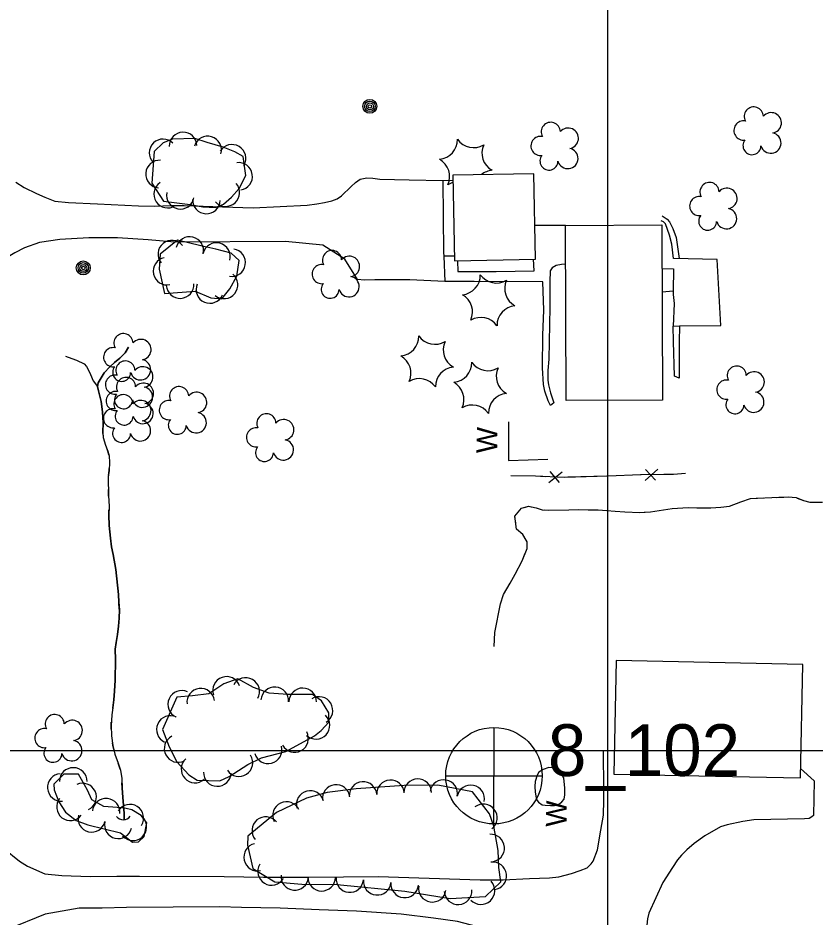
# Model space of a CAD drawing. Extents: x 591954 to 597000, y 198576 to 213500.
# Drawn here: x 594328.8 to 594560.2, y 210451.7 to 210712.6 of the extents above; entities that cross this region are included whole.
import ezdxf

# ---------------------------------------------------------------- set-up
doc = ezdxf.new("R2010")
doc.units = 0
for name, color, linetype in [('Level 10', 7, 'Continuous'), ('Level 12', 7, 'Continuous'), ('Level 14', 7, 'Continuous'), ('Level 15', 7, 'Continuous'), ('Level 17', 7, 'Continuous'), ('Level 18', 7, 'Continuous'), ('Level 19', 7, 'Continuous'), ('Level 4', 7, 'Continuous')]:
    doc.layers.add(name, color=color, linetype=linetype)

msp = doc.modelspace()

# ---------------------------------------------------------------- linework, layer by layer
at = {"layer": 'Level 10'}
for p, q in [((594500, 210000), (594500, 211500)), ((593000, 210500), (595000, 210500)), ((593000, 210500), (595000, 210500)), ((594500, 209500), (594500, 210500))]:
    msp.add_line(p, q, dxfattribs=at)
at = {"layer": 'Level 12'}
for points in [[(594478.54, 210667.39), (594455.06, 210666.95), (594455.53, 210642.11), (594479.01, 210642.55), (594478.54, 210667.39)], [(594487.7, 210652.35), (594515.66, 210652.5), (594515.94, 210601.7), (594487.97, 210601.55), (594487.7, 210652.35)], [(594515.73, 210639.84), (594519.11, 210639.82), (594518.98, 210633.26), (594515.77, 210633.05)], [(594556.61, 210524.94), (594502.48, 210526.08), (594501.79, 210493.18), (594555.92, 210492.04), (594556.61, 210524.94)]]:
    msp.add_lwpolyline(points, dxfattribs=at)
at = {"layer": 'Level 14'}
for centre, radius in [((594430.96, 210686.93), 2.02), ((594430.96, 210686.94), 1.52), ((594430.97, 210686.9), 1.01), ((594430.97, 210686.91), 0.502), ((594347.79, 210640.04), 2.02), ((594347.79, 210640.05), 1.52), ((594347.8, 210640.01), 1.01), ((594347.8, 210640.02), 0.502)]:
    msp.add_circle(centre, radius, dxfattribs=at)
at = {"layer": 'Level 15'}
for p, q in [((594482.94, 210577.78), (594486.78, 210580.88)), ((594483.23, 210581.01), (594485.91, 210577.74)), ((594510.88, 210578.33), (594514.55, 210581.63)), ((594511, 210581.58), (594513.84, 210578.45))]:
    msp.add_line(p, q, dxfattribs=at)
for points in [[(594471.18, 210595.36), (594471.18, 210584.16), (594482.63, 210584.55)], [(594471.9, 210579.82), (594479.01, 210579.67), (594487.43, 210579.36), (594500.13, 210579.72), (594509.47, 210580.05), (594519.1, 210580.2), (594522.54, 210580.52)], [(594471.9, 210579.82), (594479.01, 210579.67), (594481.85, 210579.56)], [(594488.43, 210579.39), (594499.74, 210579.71)], [(594499.74, 210579.71), (594500.13, 210579.72), (594509.47, 210580.05), (594509.69, 210580.05)], [(594516.28, 210580.16), (594519.1, 210580.2), (594522.54, 210580.52)], [(594487.26, 210492.09), (594485.82, 210494.45), (594484.38, 210494.99), (594482.88, 210495.1), (594481.22, 210494.53), (594479.99, 210493.7), (594479.53, 210492.85), (594478.93, 210490.99), (594478.86, 210489.54), (594478.96, 210487.93), (594479.24, 210486.31), (594479.57, 210485.52), (594479.94, 210484.99), (594480.93, 210484.26), (594481.86, 210484.1), (594483.4, 210484.06), (594484.53, 210484.08), (594485.43, 210484.23), (594486.15, 210484.61), (594486.72, 210485.12), (594487.36, 210485.9), (594487.55, 210487.14), (594487.55, 210487.97), (594487.54, 210489.05)], [(594487.54, 210489.05), (594487.26, 210492.09)]]:
    msp.add_lwpolyline(points, dxfattribs=at)
msp.add_arc((594359.4, 210482.39), 2.5, 217.7649, 324.0045, dxfattribs=at)
at = {"layer": 'Level 17'}
for points in [[(594328.2, 210664.89), (594330.67, 210663.33), (594334.18, 210661.64), (594336.66, 210660.6), (594339.55, 210659.41), (594343.47, 210659.02), (594351.91, 210658.59), (594363.84, 210658.05), (594368.42, 210657.99), (594373.17, 210658.11), (594377.07, 210658.12), (594388.15, 210657.73), (594397.09, 210657.47), (594412.81, 210658.27), (594415.61, 210658.63), (594417.84, 210659.07), (594419.91, 210659.54), (594421.5, 210660.13), (594422.7, 210660.92), (594425.54, 210663.71), (594426.75, 210664.82), (594428.19, 210665.78), (594430.05, 210666.17), (594431.79, 210666.04), (594433.86, 210665.78), (594442.37, 210665.64), (594452.13, 210665.44)], [(594452.13, 210665.44), (594455.09, 210665.48)], [(594452.13, 210665.44), (594452.32, 210644.51), (594452.43, 210643.41)], [(594519.14, 210642.78), (594518.64, 210646.92), (594517.93, 210649.56), (594516.75, 210652.82), (594516.18, 210653.43), (594515.53, 210653.75)], [(594515.77, 210655.2), (594517.23, 210654.23), (594517.92, 210653.42), (594518.89, 210651.49), (594519.86, 210648.86), (594520.71, 210642.75)], [(594487.7, 210652.33), (594478.83, 210652.32)], [(594357.68, 210648.76), (594349.37, 210648.82), (594341.03, 210648.32), (594335.11, 210647.41), (594330.77, 210645.84), (594327.89, 210644.39), (594326.51, 210643.53), (594325.33, 210642.65), (594323.31, 210640.75)], [(594452.68, 210636.09), (594442.55, 210636.61), (594432.41, 210636.63), (594429.39, 210636.44), (594427.35, 210636.71), (594423.69, 210642.56), (594417.28, 210646.62), (594406.44, 210647.68), (594374.3, 210647.55), (594366.58, 210648.17), (594357.68, 210648.76)], [(594455.51, 210643.45), (594452.43, 210643.41)], [(594452.43, 210643.41), (594452.68, 210636.09)], [(594456.43, 210642.13), (594456.45, 210639.01), (594467.58, 210639.02), (594478.67, 210639.2), (594478.47, 210642.55)], [(594518.98, 210633.26), (594518.98, 210632.31), (594519.29, 210629.71), (594518.98, 210623.15), (594520.82, 210623.23), (594532.86, 210623.29), (594531.76, 210642.53), (594519.14, 210642.78)], [(594487.76, 210641.12), (594486.57, 210641.08), (594485.04, 210640.76), (594483.84, 210640.08), (594483.25, 210639.15), (594483.21, 210635.99), (594483.21, 210628.67), (594482.95, 210613.58), (594482.6, 210610.3), (594482.61, 210607.49), (594482.81, 210606.11), (594483.37, 210603.8), (594484.06, 210601.72), (594484.35, 210600.92), (594483.41, 210600.14), (594482.71, 210601.46), (594481.77, 210604.25), (594481.38, 210606.24), (594481.04, 210611.03), (594481.15, 210620.51), (594481.49, 210627.75), (594481.2, 210636.02), (594461.25, 210636.12), (594452.68, 210636.09)], [(594519.39, 210608.59), (594519.13, 210618.7), (594518.98, 210623.16)], [(594520.82, 210623.23), (594520.78, 210618.64), (594520.71, 210608.06), (594519.39, 210608.59)], [(594498.92, 210488.71), (594498.73, 210499.93), (594501.94, 210500.08)], [(594559.93, 210491.23), (594555.97, 210494.83)], [(594559.93, 210491.23), (594559.72, 210481.18), (594559.28, 210480.74), (594558.48, 210480.31), (594557.1, 210480.19), (594542.37, 210479.92), (594539.17, 210479.39), (594534.67, 210478.48), (594532.74, 210477.81), (594528.2, 210475.21), (594525.07, 210473.01), (594522.99, 210471.2), (594521.4, 210469.61), (594520.25, 210468.28), (594518.79, 210466.08), (594516.03, 210461.73), (594511.96, 210452.83), (594511.57, 210451.2), (594510.21, 210438.17), (594509.28, 210424.01), (594508.43, 210412.49), (594500.24, 210412.55)], [(594324.69, 210471.61), (594329.24, 210467.93), (594331.56, 210466.43), (594336.62, 210464.23), (594341.54, 210463.71), (594349.83, 210463.48), (594357.51, 210463.56), (594364.07, 210463.52), (594388.67, 210463.4), (594400.13, 210463.27), (594413.27, 210463.26), (594433.36, 210463.43), (594463.02, 210462.51), (594469.69, 210462.45), (594477.3, 210462.88), (594483.06, 210463.09), (594485.84, 210463.33), (594489.49, 210464.3), (594492.03, 210465.15), (594493.99, 210465.99), (594495.17, 210467.1), (594495.78, 210467.9), (594496.99, 210471.16), (594497.98, 210476.92), (594498.76, 210481.22), (594498.92, 210485.56), (594498.92, 210488.71)], [(594478.3, 210413.08), (594478.16, 210414.7), (594477.11, 210432.33), (594475.7, 210440.7), (594474.65, 210442.4), (594473.14, 210444.01), (594471.33, 210445.28), (594464.1, 210448.4), (594456.4, 210450.38), (594449.44, 210451.4), (594440.02, 210452.52), (594427.11, 210453.36), (594416.29, 210453.79), (594404.9, 210454.25), (594393.69, 210454.49), (594387.41, 210454.61), (594360.3, 210454.44), (594353.28, 210454.29), (594346.56, 210454.21), (594336.68, 210452.55), (594325.77, 210448.11)]]:
    msp.add_lwpolyline(points, dxfattribs=at)
at = {"layer": 'Level 18'}
for points in [[(594371.11, 210659.38), (594378.85, 210658.43), (594382.47, 210657.72), (594386.19, 210657.57), (594388.52, 210658.51), (594390.8, 210660.56), (594393, 210663.1), (594394.97, 210666.9), (594394.15, 210672.39), (594391.82, 210673.77), (594388.38, 210675.1), (594383.78, 210676.48), (594380.18, 210677.63), (594373.72, 210677.43), (594370.96, 210676.35), (594368.32, 210673.79), (594367.65, 210664.64), (594371.11, 210659.38)], [(594371.34, 210632.64), (594380.27, 210633.34), (594384.84, 210631.35), (594388.01, 210631.07), (594390.36, 210633.94), (594392.34, 210637.63), (594393.06, 210642.15), (594390.69, 210644.36), (594386.26, 210645.52), (594381.9, 210646.47), (594375.13, 210648.08), (594370.13, 210644.02), (594369.84, 210639.64), (594371.34, 210632.64)], [(594406.61, 210499.74), (594414.85, 210504.23), (594416.82, 210505.82), (594419.03, 210508.2), (594419.06, 210510.96), (594416.96, 210514.4), (594414.27, 210516.21), (594407.19, 210516.25), (594401.7, 210516.65), (594397.19, 210518.25), (594392.65, 210520.8), (594388.57, 210519.39), (594384.23, 210516.41), (594379.5, 210515.85), (594374.99, 210515.46), (594370.74, 210506.08), (594372.7, 210501.03), (594374.96, 210496.72), (594378.4, 210492.9), (594380.8, 210491.41), (594387.45, 210491.18), (594390.15, 210492.48), (594395.51, 210495.94), (594399.56, 210497.85), (594406.61, 210499.74)], [(594362.07, 210473.42), (594363.78, 210473.5), (594365.43, 210475.02), (594366.23, 210478.99), (594364.6, 210481.12), (594361.9, 210482.81), (594360.25, 210483.2), (594357.61, 210483.44), (594353.72, 210483.8), (594350.28, 210485.74), (594348.98, 210488.49), (594346.44, 210493.1), (594342.15, 210493.14), (594339.22, 210490.26), (594339.36, 210488.55), (594340.74, 210485.11), (594342.6, 210482.16), (594345.76, 210479.71), (594349.11, 210478.43), (594358.6, 210476.1), (594362.07, 210473.42)], [(594466.97, 210478.02), (594465.69, 210481.6), (594460.74, 210488), (594450.69, 210489.95), (594440.96, 210489.81), (594426.96, 210488.91), (594418.61, 210487.84), (594412.6, 210486.22), (594403.85, 210482.04), (594395.51, 210475.15)], [(594395.51, 210475.15), (594395.47, 210472.49), (594397, 210465.75), (594403.4, 210461.88), (594411.2, 210461.19), (594421.47, 210461.09), (594441.16, 210459.18), (594454.28, 210457.08), (594464.53, 210457.69), (594468.98, 210461.85), (594468.42, 210466.01), (594468.18, 210471.01), (594466.97, 210478.02)]]:
    msp.add_lwpolyline(points, dxfattribs=at)
for centre, radius, start, end in [((594542.4, 210683.99), 2.78, 1.3946, 209.1675), ((594547.45, 210682.13), 2.97, 278.4237, 139.6575), ((594483.48, 210679.52), 2.78, 1.3946, 209.1675), ((594539.4, 210679.91), 2.78, 78.0716, 279.0826), ((594488.53, 210677.66), 2.97, 278.4237, 139.6575), ((594547.33, 210676.28), 2.97, 196.0745, 79.0477), ((594450.66, 210677.29), 5.72, 275.2113, 0.9762), ((594461.06, 210680.68), 5.72, 215.2113, 300.9762), ((594480.48, 210675.44), 2.78, 78.0716, 279.0826), ((594541.87, 210675.51), 2.61, 140.7797, 358.7123), ((594390.96, 210671.84), 4, 329.4135, 149.3982), ((594469.21, 210673.37), 5.72, 155.2113, 240.9762), ((594488.42, 210671.81), 2.97, 196.0745, 79.0477), ((594448.41, 210666.58), 5.72, 335.2113, 60.9762), ((594482.95, 210671.04), 2.61, 140.7797, 358.7123), ((594466.95, 210662.67), 5.72, 95.2113, 129.2172), ((594456.55, 210659.27), 5.72, 104.6616, 120.9762), ((594529.55, 210662.07), 2.78, 1.3946, 209.1675), ((594534.59, 210660.21), 2.97, 278.4237, 139.6575), ((594526.55, 210658), 2.78, 78.0716, 279.0826), ((594529.01, 210653.6), 2.61, 140.7797, 358.7123), ((594534.48, 210654.36), 2.97, 196.0745, 79.0477), ((594419.98, 210642.32), 2.78, 1.3946, 209.1675), ((594425.02, 210640.46), 2.97, 278.4237, 139.6575), ((594416.98, 210638.24), 2.78, 78.0716, 279.0826), ((594424.91, 210634.61), 2.97, 196.0745, 79.0477), ((594457.3, 210637.96), 5.72, 275.2113, 0.9762), ((594467.7, 210641.36), 5.72, 215.2113, 300.9762), ((594384.52, 210633.78), 4, 156.5045, 336.4892), ((594419.44, 210633.84), 2.61, 140.7797, 358.7123), ((594475.84, 210634.05), 5.72, 155.2113, 240.9762), ((594455.04, 210627.26), 5.72, 335.2113, 60.9762), ((594473.59, 210623.35), 5.72, 95.2113, 180.9762), ((594463.18, 210619.95), 5.72, 35.2113, 120.9762), ((594359.46, 210618.21), 2.78, 1.3946, 209.1675), ((594364.51, 210616.35), 2.97, 278.4237, 139.6575), ((594439.44, 210620.21), 5.72, 275.2113, 0.9762), ((594449.84, 210623.6), 5.72, 215.2113, 300.9762), ((594457.98, 210616.29), 5.72, 155.2113, 240.9762), ((594356.46, 210614.13), 2.78, 78.0716, 279.0826), ((594437.18, 210609.5), 5.72, 335.2113, 60.9762), ((594358.93, 210609.73), 2.61, 140.7797, 358.7123), ((594360.01, 210610.26), 2.78, 1.3946, 209.1675), ((594364.4, 210610.5), 2.97, 196.0745, 79.0477), ((594365.05, 210608.4), 2.97, 278.4237, 139.6575), ((594455.72, 210605.59), 5.72, 95.2113, 180.9762), ((594454.82, 210612.55), 5.72, 275.2113, 0.9762), ((594465.22, 210615.94), 5.72, 215.2113, 300.9762), ((594473.36, 210608.64), 5.72, 155.2113, 240.9762), ((594537.45, 210608.8), 2.78, 1.3946, 209.1675), ((594357.01, 210606.18), 2.78, 78.0716, 279.0826), ((594360.19, 210605.51), 2.78, 1.3946, 209.1675), ((594542.49, 210606.94), 2.97, 278.4237, 139.6575), ((594365.23, 210603.65), 2.97, 278.4237, 139.6575), ((594445.32, 210602.19), 5.72, 35.2113, 120.9762), ((594452.56, 210601.84), 5.72, 335.2113, 60.9762), ((594534.45, 210604.72), 2.78, 78.0716, 279.0826), ((594357.19, 210601.43), 2.78, 78.0716, 279.0826), ((594359.43, 210600.5), 2.78, 1.3946, 209.1675), ((594359.47, 210601.79), 2.61, 140.7797, 358.7123), ((594364.94, 210602.55), 2.97, 196.0745, 79.0477), ((594375.61, 210602.84), 2.78, 1.3946, 209.1675), ((594380.66, 210600.99), 2.97, 278.4237, 139.6575), ((594471.1, 210597.93), 5.72, 95.2113, 180.9762), ((594542.38, 210601.09), 2.97, 196.0745, 79.0477), ((594364.48, 210598.64), 2.97, 278.4237, 139.6575), ((594365.12, 210597.8), 2.97, 196.0745, 79.0477), ((594372.61, 210598.77), 2.78, 78.0716, 279.0826), ((594536.91, 210600.32), 2.61, 140.7797, 358.7123), ((594356.43, 210596.42), 2.78, 78.0716, 279.0826), ((594359.65, 210597.03), 2.61, 140.7797, 358.7123), ((594380.54, 210595.13), 2.97, 196.0745, 79.0477), ((594460.7, 210594.53), 5.72, 35.2113, 120.9762), ((594364.37, 210592.78), 2.97, 196.0745, 79.0477), ((594375.08, 210594.37), 2.61, 140.7797, 358.7123), ((594400.92, 210594.95), 2.78, 1.3946, 209.1675), ((594405.96, 210593.09), 2.97, 278.4237, 139.6575), ((594358.9, 210592.02), 2.61, 140.7797, 358.7123), ((594397.92, 210590.87), 2.78, 78.0716, 279.0826), ((594405.85, 210587.24), 2.97, 196.0745, 79.0477), ((594400.38, 210586.47), 2.61, 140.7797, 358.7123), ((594339.51, 210507.67), 2.78, 1.3946, 209.1675), ((594344.56, 210505.81), 2.97, 278.4237, 139.6575), ((594336.51, 210503.59), 2.78, 78.0716, 279.0826), ((594344.44, 210499.96), 2.97, 196.0745, 79.0477), ((594338.98, 210499.19), 2.61, 140.7797, 358.7123), ((594428.99, 210486.94), 4, 3.6813, 183.666), ((594436.97, 210487.45), 4, 3.6813, 183.666), ((594444.86, 210487.77), 4, 0.8265, 180.8111), ((594452.39, 210487.49), 4, 349.0424, 169.0271), ((594413.67, 210484.34), 4, 15.0874, 195.0721), ((594421.18, 210486.06), 4, 7.293, 187.2777), ((594460.24, 210485.96), 4, 349.0424, 169.0271), ((594406.78, 210481.12), 4, 25.5482, 205.5328), ((594463.92, 210480.47), 4, 307.7671, 127.7518), ((594400.75, 210476.76), 4, 39.5764, 219.5611), ((594466.03, 210471.71), 4, 274.1234, 94.1081), ((594398.39, 210469.06), 4, 102.7498, 282.7345), ((594466.63, 210463.61), 4, 277.6854, 97.6701), ((594402.43, 210464.92), 4, 148.8468, 328.8315), ((594409.16, 210463.47), 4, 174.9153, 354.8999), ((594416.98, 210463.23), 4, 179.467, 359.4517), ((594425.15, 210462.84), 4, 174.4715, 354.4561), ((594433.11, 210462.07), 4, 174.4715, 354.4561), ((594441.07, 210461.3), 4, 174.4715, 354.4561), ((594449.1, 210460.03), 4, 170.8784, 350.8631), ((594456.57, 210459.31), 4, 183.46, 3.4447), ((594463.21, 210459.33), 4, 223.0332, 43.0179)]:
    msp.add_arc(centre, radius, start, end, dxfattribs=at)
for centre, major_axis, ratio, start_param, end_param in [((594376.76, 210675.43), (0.85, -3.91), 0.999995, 1.387066, 4.528391), ((594383.88, 210674.26), (-0.82, -3.92), 0.999998, 1.48515, 4.626476), ((594370.94, 210673.42), (-2.1, 3.41), 0.999984, 4.930469, 8.071794), ((594369.94, 210667.28), (-3.35, 2.19), 0.999997, 5.219356, 8.360681), ((594392.9, 210666.61), (-3.76, -1.35), 0.999985, 1.37348, 4.514805), ((594372.26, 210661.45), (3.17, 2.43), 0.999954, 1.499413, 4.640739), ((594389.15, 210661.89), (1.5, -3.71), 0.999994, 5.0606, 8.201926), ((594375.97, 210661.13), (0.34, 3.99), 0.999996, 1.460718, 4.602043), ((594383.52, 210659.77), (-0.35, -3.99), 0.999942, 4.758056, 7.899382), ((594373.47, 210644.04), (1.79, 3.58), 0.999993, 5.857092, 8.998417), ((594378.69, 210645.08), (1.37, 3.76), 0.999991, 4.829643, 7.970969), ((594386.44, 210643.31), (1.26, 3.8), 0.999978, 4.774869, 7.916195), ((594390.85, 210641.57), (-0.63, -3.95), 0.999992, 0, 3.141325), ((594372.1, 210639.1), (1.87, 3.53), 0.999991, 0.698441, 3.839766), ((594388.64, 210635.14), (-2.53, -3.1), 0.999993, 0, 3.141325), ((594375.89, 210635.2), (-0.81, -3.92), 0.99998, 4.972034, 8.11336), ((594389.36, 210517.45), (3.49, 1.96), 0.999233, 6.104979, 9.246304), ((594394.94, 210517.12), (3.99, 0.3), 0.999783, 5.698437, 8.839762), ((594376.35, 210513.39), (-0.17, 4), 0.999251, 5.814951, 8.956276), ((594381.87, 210514.02), (3.97, 0.47), 0.999377, 0.000134, 3.141459), ((594403.35, 210514.43), (3.67, 1.6), 0.999384, 5.799148, 8.940473), ((594411.47, 210514.13), (3.84, 1.13), 0.999417, 5.989534, 9.130859), ((594416.2, 210511.62), (-3.16, -2.46), 0.999747, 1.457817, 4.599143), ((594373.05, 210506.11), (-0.17, 4), 0.999251, 5.814951, 8.956276), ((594415.34, 210507.3), (-3.87, 1.03), 0.996501, 1.082857, 4.224183), ((594375.3, 210500.58), (3.33, 2.22), 0.998774, 1.465465, 4.60679), ((594409.12, 210503.49), (-3.35, -2.19), 0.999201, 6.203268, 9.344593), ((594401.42, 210500.2), (-3.9, -0.9), 0.999289, 0.036525, 3.17785), ((594380.22, 210494.62), (-3.11, -2.52), 0.995659, 4.765111, 7.906437), ((594392.98, 210496.46), (-1.91, -3.52), 0.998957, 5.78268, 8.924005), ((594344.88, 210491.02), (2.08, 3.42), 0.999378, 5.249591, 8.390917), ((594386.7, 210493.61), (-3.99, 0.33), 0.999487, 0.047075, 3.188401), ((594341.4, 210489.29), (-1.44, 3.73), 0.998099, 5.995146, 9.136472), ((594347.6, 210486.52), (1.18, -3.82), 0.998869, 0.138663, 3.279989), ((594344.06, 210483.67), (-3.16, 2.45), 0.999747, 0.000134, 3.141459), ((594354.42, 210482.08), (0.99, 3.88), 0.996579, 4.868341, 8.009666), ((594361.33, 210480.39), (-1.41, -3.74), 0.996571, 1.371842, 4.513167), ((594350.23, 210480.32), (-1.07, -3.85), 0.992899, 4.742401, 7.883726), ((594362.17, 210477.85), (-4, 0.06), 0.996242, 0.75292, 3.894245), ((594357.94, 210478.42), (-1.07, -3.85), 0.992899, 4.742401, 7.883726)]:
    msp.add_ellipse(centre, major_axis=major_axis, ratio=ratio, start_param=start_param, end_param=end_param, dxfattribs=at)
at = {"layer": 'Level 19'}
for points in [[(594360.91, 210617.03), (594359.97, 210615.43), (594358.42, 210613.86), (594356.85, 210612.56), (594355.49, 210611.34), (594353.89, 210609.55), (594352.14, 210606.69), (594351.96, 210605.63), (594352.16, 210604.42), (594352.94, 210601.32), (594353.38, 210598.32), (594353.55, 210595.12), (594353.48, 210592.42), (594353.59, 210590.83), (594354.22, 210588.61), (594354.93, 210586.85), (594355.34, 210585.5), (594355.43, 210583.61), (594355.26, 210581.26), (594355, 210579.3), (594354.97, 210577.43), (594355.07, 210575.75), (594355.14, 210573.86), (594355.27, 210570.92), (594355.19, 210568.29), (594355.28, 210565.27), (594355.67, 210561.61), (594356.01, 210559.07), (594356.45, 210556.88), (594357.27, 210552.54), (594357.99, 210545.3), (594358.15, 210543.07), (594358.26, 210540.79), (594358.24, 210538.37), (594358.02, 210536.07), (594357.73, 210533.63), (594357.32, 210531.39), (594357.05, 210529.42), (594357.12, 210526.41), (594357.08, 210520.45), (594356.86, 210517.18), (594356.66, 210514.74), (594356.36, 210512.35), (594356.09, 210510.38), (594355.86, 210507.14), (594355.94, 210504.27), (594356.37, 210501.44), (594356.96, 210498.99), (594357.93, 210496.36), (594358.6, 210494.34), (594358.95, 210491.89), (594359.1, 210489.04), (594359.25, 210486.45), (594359.67, 210481.72), (594359.65, 210479.93)], [(594353.54, 210591.53), (594353.48, 210592.42), (594353.55, 210595.12), (594353.38, 210598.32), (594352.94, 210601.32), (594352.16, 210604.42), (594351.96, 210605.63), (594352.14, 210606.69), (594353.89, 210609.55), (594355.49, 210611.34), (594356.85, 210612.56), (594358.42, 210613.86), (594359.97, 210615.43), (594360.91, 210617.03)], [(594342.59, 210614.41), (594344.48, 210613.71), (594345.81, 210613.23), (594348.02, 210612.17), (594348.76, 210611.48), (594349.34, 210610.41), (594349.89, 210609.07), (594350.69, 210607.28), (594351.96, 210605.63)], [(594342.59, 210614.41), (594344.48, 210613.71), (594345.81, 210613.23), (594348.02, 210612.17), (594348.76, 210611.48), (594349.34, 210610.41), (594349.89, 210609.07), (594350.69, 210607.28), (594351.96, 210605.63)], [(594355.25, 210585.81), (594354.93, 210586.85), (594354.59, 210587.69)], [(594355.07, 210579.84), (594355.26, 210581.26), (594355.3, 210581.83)], [(594355.14, 210573.85), (594355.14, 210573.86), (594355.07, 210575.75), (594355.06, 210575.85)], [(594467.04, 210530.17), (594467.28, 210534.27), (594468.9, 210542.61), (594469.75, 210545.31), (594471.68, 210548.6), (594473.18, 210551.2), (594475.18, 210555.04), (594476.62, 210558.65), (594476.65, 210560.6), (594475.36, 210562.71), (594473.52, 210564.27), (594473.02, 210568.03), (594474.98, 210570.35), (594477, 210570.86), (594479.2, 210570.42), (594480.95, 210569.88), (594482.83, 210569.72), (594488.74, 210569.87), (594491.64, 210569.97), (594494.34, 210569.86), (594497.27, 210569.86), (594499.77, 210569.67), (594502.15, 210569.46), (594504.96, 210569.23), (594509.35, 210569.08), (594512.43, 210569.23), (594518.75, 210570.26), (594523.32, 210570.51), (594525.84, 210570.42), (594528.01, 210570.44), (594529.94, 210570.43), (594532.85, 210570.57), (594535.39, 210570.89), (594538.66, 210572.16), (594541.41, 210573.12), (594549.67, 210573.5), (594552.38, 210573.61), (594554.71, 210573.38), (594556.85, 210572.53), (594558.62, 210572.04), (594562.32, 210572.09)], [(594510.6, 210569.15), (594512.43, 210569.23), (594518.75, 210570.26), (594523.32, 210570.51), (594525.84, 210570.42), (594528.01, 210570.44), (594529.94, 210570.43), (594532.85, 210570.57), (594535.39, 210570.89), (594538.66, 210572.16), (594539.21, 210572.35)], [(594543.08, 210573.2), (594545.08, 210573.29)], [(594549.07, 210573.47), (594549.67, 210573.5), (594551.07, 210573.56)], [(594555.03, 210573.25), (594556.85, 210572.53), (594556.89, 210572.52)], [(594358.25, 210541.06), (594358.15, 210543.07), (594357.99, 210545.3), (594357.27, 210552.54), (594356.45, 210556.88), (594356.01, 210559.07), (594355.67, 210561.61), (594355.28, 210565.27), (594355.19, 210568.29), (594355.24, 210569.85)], [(594475.81, 210570.56), (594477, 210570.86), (594477.75, 210570.71)], [(594481.64, 210569.82), (594482.83, 210569.72), (594488.74, 210569.87), (594491.64, 210569.97), (594494.34, 210569.86), (594497.27, 210569.86), (594499.77, 210569.67), (594502.15, 210569.46), (594504.96, 210569.23), (594509.35, 210569.08), (594510.6, 210569.15)], [(594473.29, 210565.94), (594473.03, 210567.93)], [(594476.35, 210561.09), (594475.36, 210562.71), (594475.28, 210562.78)], [(594467.04, 210530.17), (594467.28, 210534.27), (594468.9, 210542.61), (594469.75, 210545.31), (594471.68, 210548.6), (594473.18, 210551.2), (594475.18, 210555.04), (594476.08, 210557.28)], [(594356.34, 210512.18), (594356.36, 210512.35), (594356.66, 210514.74), (594356.86, 210517.18), (594357.08, 210520.45), (594357.12, 210526.41), (594357.05, 210529.42), (594357.32, 210531.39), (594357.73, 210533.63), (594358.02, 210536.07), (594358.24, 210538.37), (594358.26, 210540.79), (594358.25, 210541.06)], [(594355.88, 210506.21), (594355.86, 210507.14), (594355.93, 210508.21)], [(594356.65, 210500.28), (594356.37, 210501.44), (594356.25, 210502.23)], [(594358.52, 210494.58), (594357.93, 210496.36), (594357.88, 210496.48)], [(594359.65, 210479.93), (594359.67, 210481.72), (594359.25, 210486.45), (594359.1, 210489.04), (594359.01, 210490.62)]]:
    msp.add_lwpolyline(points, dxfattribs=at)
at = {"layer": 'Level 4'}
for p, q in [((594466.94, 210506.71), (594466.87, 210478.86)), ((594466.94, 210506.71), (594466.87, 210478.86)), ((594453.03, 210492.68), (594480.93, 210492.67)), ((594453.03, 210492.68), (594480.93, 210492.67))]:
    msp.add_line(p, q, dxfattribs=at)
msp.add_circle((594466.99, 210492.69), 14, dxfattribs=at)
msp.add_circle((594466.99, 210492.69), 14, dxfattribs=at)

# ---------------------------------------------------------------- texts
at = {"layer": 'Level 15'}
for rotation, p in [(88.9534, (594467.89, 210586.22)), (89.0379, (594488.03, 210477.83))]:
    msp.add_text('W', height=6, rotation=rotation, dxfattribs=at).set_placement(p)
at = {"layer": 'Level 4'}
msp.add_text('8_102', height=15, dxfattribs=at).set_placement((594482.64, 210492.62))
msp.add_text('8_102', height=15, dxfattribs=at).set_placement((594482.64, 210492.62))

doc.saveas('drawing.dxf')
